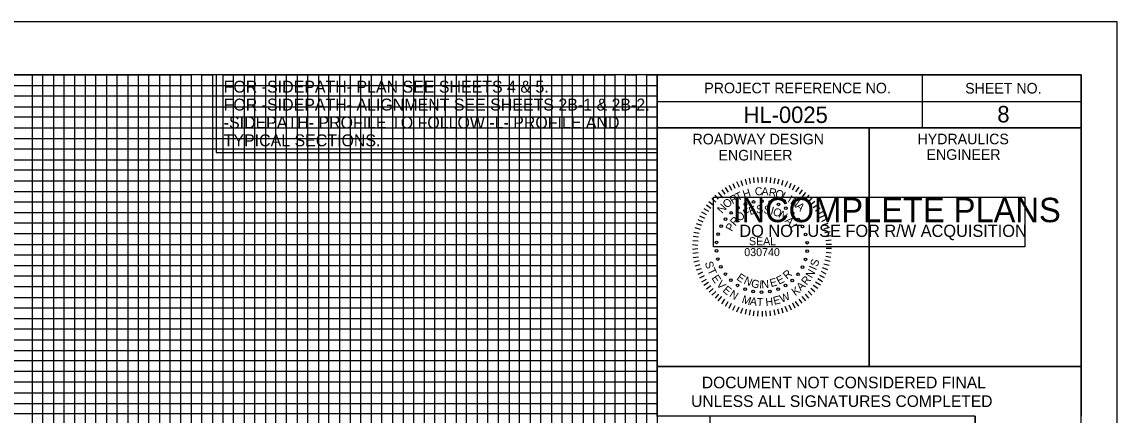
# Model space of a CAD drawing. Extents: x 1524869 to 1526553, y 501099 to 502199.
# Drawn here: x 1526036 to 1526553, y 502013 to 502199 of the extents above; entities that cross this region are included whole.
import ezdxf

# ---------------------------------------------------------------- set-up
doc = ezdxf.new("R2010")
doc.units = 0
for name, color, linetype in [('Old_Level_9', 7, 'Continuous'), ('Prop Grid Mask', 7, 'Continuous'), ('Prop Horizontal Alignment Curve and Spiral Data', 7, 'Continuous'), ('Sheet Data Field CELL', 7, 'Continuous'), ('Sheet Layout Profile Border Port 1', 7, 'Continuous'), ('Sheet Plot Border Outside CELL', 7, 'Continuous'), ('Sheet Profile CELL', 7, 'Continuous'), ('Sheet Profile Grid Major CELL', 7, 'Continuous'), ('Sheet Profile Grid Middle CELL', 7, 'Continuous'), ('Sheet Profile Grid Minor CELL', 7, 'Continuous'), ('Sheet Sticker Exception Certification CELL', 7, 'Continuous'), ('Sheet Sticker Incomplete CELL', 7, 'Continuous')]:
    doc.layers.add(name, color=color, linetype=linetype)

msp = doc.modelspace()

# ---------------------------------------------------------------- linework, layer by layer
at = {"layer": 'Old_Level_9'}
for p, q in [((1526369.96, 502121.58), (1526371.16, 502119.18)), ((1526371.76, 502122.38), (1526372.66, 502120.08)), ((1526373.46, 502123.18), (1526374.66, 502120.78)), ((1526375.56, 502123.78), (1526376.26, 502121.38)), ((1526377.46, 502124.38), (1526378.16, 502121.88)), ((1526379.36, 502124.78), (1526379.86, 502122.38)), ((1526381.46, 502125.08), (1526381.66, 502122.68)), ((1526383.36, 502125.18), (1526383.66, 502122.78)), ((1526385.46, 502125.38), (1526385.46, 502122.78)), ((1526387.56, 502125.38), (1526387.26, 502122.78)), ((1526389.46, 502125.08), (1526389.26, 502122.68)), ((1526391.56, 502124.78), (1526391.06, 502122.38)), ((1526393.46, 502124.38), (1526392.76, 502121.98)), ((1526395.36, 502123.78), (1526394.66, 502121.38)), ((1526397.46, 502123.18), (1526396.26, 502120.78)), ((1526399.16, 502122.38), (1526398.26, 502120.08)), ((1526400.96, 502121.58), (1526399.76, 502119.18)), ((1526363.26, 502116.78), (1526364.86, 502114.88)), ((1526364.86, 502118.08), (1526366.46, 502115.98)), ((1526366.46, 502119.28), (1526367.96, 502117.28)), ((1526368.06, 502120.38), (1526369.56, 502118.18)), ((1526402.86, 502120.58), (1526401.36, 502118.38)), ((1526404.46, 502119.28), (1526402.96, 502117.28)), ((1526406.06, 502118.08), (1526404.46, 502116.08)), ((1526407.66, 502116.78), (1526406.06, 502114.98)), ((1526409.06, 502115.48), (1526407.26, 502113.58)), ((1526358.06, 502110.58), (1526360.26, 502109.28)), ((1526359.36, 502112.28), (1526361.26, 502110.68)), ((1526360.46, 502113.88), (1526362.36, 502112.18)), ((1526361.86, 502115.28), (1526363.66, 502113.58)), ((1526410.46, 502113.88), (1526408.56, 502112.28)), ((1526411.76, 502112.28), (1526409.66, 502110.88)), ((1526412.86, 502110.68), (1526410.76, 502109.28)), ((1526355.16, 502105.28), (1526357.56, 502104.28)), ((1526355.96, 502107.08), (1526358.36, 502105.88)), ((1526356.96, 502108.98), (1526359.16, 502107.68)), ((1526413.96, 502108.98), (1526411.76, 502107.68)), ((1526414.96, 502107.18), (1526412.56, 502106.08)), ((1526415.76, 502105.48), (1526413.56, 502104.28)), ((1526353.76, 502101.48), (1526356.26, 502100.78)), ((1526354.36, 502103.38), (1526356.96, 502102.58)), ((1526416.56, 502103.38), (1526413.96, 502102.58)), ((1526417.16, 502101.48), (1526414.66, 502100.78)), ((1526352.76, 502095.38), (1526355.36, 502095.28)), ((1526352.96, 502097.48), (1526355.46, 502097.18)), ((1526353.26, 502099.38), (1526355.76, 502098.88)), ((1526417.66, 502099.58), (1526415.16, 502099.08)), ((1526417.96, 502097.68), (1526415.56, 502097.18)), ((1526418.16, 502095.58), (1526415.56, 502095.28)), ((1526352.66, 502093.48), (1526355.16, 502093.28)), ((1526352.66, 502091.38), (1526355.16, 502091.58)), ((1526352.76, 502089.38), (1526355.36, 502089.68)), ((1526418.26, 502093.48), (1526415.76, 502093.48)), ((1526418.26, 502091.58), (1526415.76, 502091.58)), ((1526418.16, 502089.48), (1526415.76, 502089.68)), ((1526352.96, 502087.38), (1526355.46, 502087.78)), ((1526353.26, 502085.38), (1526355.76, 502085.98)), ((1526417.66, 502085.48), (1526415.16, 502086.18)), ((1526417.96, 502087.38), (1526415.56, 502087.88)), ((1526353.86, 502083.48), (1526356.26, 502084.08)), ((1526354.56, 502081.58), (1526356.96, 502082.28)), ((1526355.36, 502079.58), (1526357.56, 502080.58)), ((1526415.76, 502079.58), (1526413.56, 502080.78)), ((1526416.56, 502081.58), (1526413.96, 502082.48)), ((1526417.16, 502083.58), (1526414.66, 502084.28)), ((1526356.16, 502077.88), (1526358.36, 502078.98)), ((1526357.06, 502075.98), (1526359.36, 502077.18)), ((1526358.06, 502074.38), (1526360.26, 502075.68)), ((1526359.36, 502072.58), (1526361.36, 502074.18)), ((1526411.76, 502072.78), (1526409.66, 502074.18)), ((1526413.06, 502074.38), (1526410.76, 502075.78)), ((1526413.96, 502075.98), (1526411.76, 502077.38)), ((1526414.96, 502077.88), (1526412.76, 502078.98)), ((1526360.56, 502070.98), (1526362.46, 502072.78)), ((1526361.86, 502069.58), (1526363.76, 502071.28)), ((1526363.46, 502068.18), (1526365.06, 502070.08)), ((1526364.86, 502066.88), (1526366.46, 502068.98)), ((1526406.16, 502066.88), (1526404.46, 502068.98)), ((1526407.66, 502068.28), (1526406.06, 502070.08)), ((1526409.06, 502069.58), (1526407.26, 502071.48)), ((1526410.46, 502071.18), (1526408.56, 502072.78)), ((1526366.46, 502065.58), (1526367.96, 502067.68)), ((1526368.26, 502064.48), (1526369.56, 502066.68)), ((1526369.96, 502063.48), (1526371.16, 502065.78)), ((1526371.76, 502062.58), (1526372.86, 502064.78)), ((1526373.66, 502061.78), (1526374.66, 502064.18)), ((1526397.46, 502061.78), (1526396.46, 502064.28)), ((1526399.36, 502062.58), (1526398.26, 502064.98)), ((1526401.06, 502063.48), (1526399.96, 502065.78)), ((1526402.86, 502064.48), (1526401.36, 502066.68)), ((1526404.46, 502065.78), (1526402.96, 502067.78)), ((1526375.56, 502061.08), (1526376.36, 502063.48)), ((1526377.66, 502060.68), (1526378.16, 502063.08)), ((1526379.56, 502060.18), (1526380.06, 502062.68)), ((1526381.46, 502059.88), (1526381.76, 502062.28)), ((1526383.56, 502059.68), (1526383.66, 502062.28)), ((1526385.66, 502059.58), (1526385.66, 502062.08)), ((1526387.56, 502059.68), (1526387.36, 502062.28)), ((1526389.56, 502059.88), (1526389.26, 502062.28)), ((1526391.66, 502060.18), (1526391.16, 502062.68)), ((1526393.56, 502060.68), (1526392.96, 502063.08)), ((1526395.46, 502061.08), (1526394.86, 502063.48))]:
    msp.add_line(p, q, dxfattribs=at)
for centre in [(1526374.13, 502110.79), (1526377.69, 502112.54), (1526381.51, 502113.61), (1526385.46, 502113.96), (1526389.41, 502113.58), (1526393.22, 502112.48), (1526396.76, 502110.7), (1526368.28, 502105.49), (1526370.96, 502108.41), (1526399.91, 502108.3), (1526402.57, 502105.36), (1526366.18, 502102.13), (1526404.65, 502101.98), (1526363.98, 502094.54), (1526364.73, 502098.44), (1526406.07, 502098.28), (1526406.78, 502094.38), (1526363.97, 502090.58), (1526406.76, 502090.41), (1526364.68, 502086.68), (1526406.02, 502086.51), (1526366.1, 502082.97), (1526368.18, 502079.59), (1526402.47, 502079.46), (1526404.57, 502082.82), (1526370.84, 502076.65), (1526373.99, 502074.25), (1526396.61, 502074.16), (1526399.79, 502076.54), (1526377.53, 502072.47), (1526381.34, 502071.37), (1526385.29, 502070.99), (1526389.24, 502071.34), (1526393.06, 502072.41)]:
    msp.add_circle(centre, 0.63, dxfattribs=at)
at = {"layer": 'Prop Grid Mask'}
msp.add_lwpolyline([(1526127.84, 502137.02), (1526336.03, 502137.02), (1526336.03, 502173.56), (1526127.84, 502173.56)], close=True, dxfattribs=at)
at = {"layer": 'Sheet Layout Profile Border Port 1'}
msp.add_lwpolyline([(1525086.08, 502173.56), (1525086.08, 501673.56), (1526486.08, 501673.56), (1526486.08, 502012.51), (1526336.03, 502012.51), (1526336.08, 502173.56)], close=True, dxfattribs=at)
at = {"layer": 'Sheet Plot Border Outside CELL'}
msp.add_lwpolyline([(1524869.08, 501098.56), (1526553.08, 501098.56), (1526553.08, 502198.56), (1524869.08, 502198.56)], close=True, dxfattribs=at)
at = {"layer": 'Sheet Profile CELL'}
for p, q in [((1526461.08, 502173.51), (1526461.08, 502148.51)), ((1526336.03, 502161.01), (1526536.08, 502161.01)), ((1526436.08, 502148.51), (1526436.08, 502036.06))]:
    msp.add_line(p, q, dxfattribs=at)
for points in [[(1526536.08, 502173.56), (1525036.08, 502173.56), (1525036.08, 501123.56), (1526536.08, 501123.56)], [(1526336.03, 502173.56), (1526536.08, 502173.56), (1526536.08, 502148.51), (1526336.03, 502148.51)], [(1526336.03, 502148.51), (1526436.08, 502148.51), (1526436.08, 502036.01), (1526336.03, 502036.01)], [(1526436.08, 502148.51), (1526536.08, 502148.51), (1526536.08, 502036.01), (1526436.08, 502036.01)]]:
    msp.add_lwpolyline(points, close=True, dxfattribs=at)
at = {"layer": 'Sheet Profile Grid Major CELL'}
for p, q in [((1526186.03, 502173.56), (1526236.03, 502173.56)), ((1526226.97, 502173.56), (1526276.97, 502173.56))]:
    msp.add_line(p, q, dxfattribs=at)
for points in [[(1526036.08, 502173.56), (1526086.08, 502173.56), (1526086.08, 501673.56), (1526136.08, 501673.56), (1526136.08, 502173.56), (1526186.08, 502173.56), (1526186.08, 501673.56), (1526236.08, 501673.56), (1526236.08, 502173.56), (1526286.08, 502173.56), (1526286.08, 501673.56), (1526336.08, 501673.56), (1526336.08, 502173.56), (1526362.38, 502173.56)], [(1525036.08, 502123.56), (1526336.08, 502123.56)], [(1526336.08, 502073.56), (1525036.08, 502073.56), (1525036.08, 502023.56), (1526336.08, 502023.56)], [(1526486.08, 502012.51), (1526486.08, 501673.56), (1526536.08, 501673.56), (1526536.08, 502023.56)]]:
    msp.add_lwpolyline(points, dxfattribs=at)
at = {"layer": 'Sheet Profile Grid Middle CELL'}
msp.add_line((1525036.08, 502148.56), (1526336.03, 502148.56), dxfattribs=at)
for points in [[(1526011.08, 501673.56), (1526061.08, 501673.56), (1526061.08, 502173.56), (1526111.08, 502173.56), (1526111.08, 501673.56), (1526161.08, 501673.56), (1526161.08, 502173.56), (1526211.08, 502173.56), (1526211.08, 501673.56), (1526261.08, 501673.56), (1526261.08, 502173.56), (1526311.08, 502173.56), (1526311.08, 501673.56), (1526361.08, 501673.56), (1526361.08, 502012.51)], [(1526336.08, 502098.56), (1525036.08, 502098.56), (1525036.08, 502048.56), (1526336.08, 502048.56)]]:
    msp.add_lwpolyline(points, dxfattribs=at)
at = {"layer": 'Sheet Profile Grid Minor CELL'}
for p, q in [((1525086.08, 502168.56), (1526336.08, 502168.56)), ((1526336.08, 502163.56), (1525086.08, 502163.21)), ((1525086.08, 502158.56), (1526336.08, 502158.56)), ((1526336.03, 502038.56), (1525086.08, 502038.56)), ((1526336.08, 502033.56), (1525086.08, 502033.56)), ((1526336.08, 502028.56), (1525086.08, 502028.56)), ((1525086.08, 502018.56), (1526336.08, 502018.56)), ((1526336.08, 502013.56), (1525086.08, 502013.56))]:
    msp.add_line(p, q, dxfattribs=at)
for points in [[(1526031.08, 502173.56), (1526041.08, 502173.56), (1526041.08, 501673.56)], [(1526046.08, 501673.56), (1526046.08, 502173.56), (1526051.08, 502173.56), (1526051.08, 501673.56)], [(1526056.08, 501673.56), (1526056.08, 502173.56), (1526066.08, 502173.56), (1526066.08, 501673.56)], [(1526071.08, 501673.56), (1526071.08, 502173.56), (1526076.08, 502173.56), (1526076.08, 501673.56)], [(1526081.08, 501673.56), (1526081.08, 502173.56), (1526091.08, 502173.56), (1526091.08, 501673.56)], [(1526096.08, 501673.56), (1526096.08, 502173.56), (1526101.08, 502173.56), (1526101.08, 501673.56)], [(1526106.08, 501673.56), (1526106.08, 502173.56), (1526116.08, 502173.56), (1526116.08, 501673.56)], [(1526121.08, 501673.56), (1526121.08, 502173.56), (1526126.08, 502173.56), (1526126.08, 501673.56)], [(1526131.08, 501673.56), (1526131.08, 502173.56), (1526141.08, 502173.56), (1526141.08, 501673.56)], [(1526146.08, 501673.56), (1526146.08, 502173.56), (1526151.08, 502173.56), (1526151.08, 501673.56)], [(1526156.08, 501673.56), (1526156.08, 502173.56), (1526166.08, 502173.56), (1526166.08, 501673.56)], [(1526171.08, 501673.56), (1526171.08, 502173.56), (1526176.08, 502173.56), (1526176.08, 501673.56)], [(1526181.08, 501673.56), (1526181.08, 502173.56), (1526191.08, 502173.56), (1526191.08, 501673.56)], [(1526196.08, 501673.56), (1526196.08, 502173.56), (1526201.08, 502173.56), (1526201.08, 501673.56)], [(1526206.08, 501673.56), (1526206.08, 502173.56), (1526216.08, 502173.56), (1526216.08, 501673.56)], [(1526221.08, 501673.56), (1526221.08, 502173.56), (1526226.08, 502173.56), (1526226.08, 501673.56)], [(1526231.08, 501673.56), (1526231.08, 502173.56), (1526241.08, 502173.56), (1526241.08, 501673.56)], [(1526246.08, 501673.56), (1526246.08, 502173.56), (1526251.08, 502173.56), (1526251.08, 501673.56)], [(1526256.08, 501673.56), (1526256.08, 502173.56), (1526266.08, 502173.56), (1526266.08, 501673.56)], [(1526271.08, 501673.56), (1526271.08, 502173.56), (1526276.08, 502173.56), (1526276.08, 501673.56)], [(1526281.08, 501673.56), (1526281.08, 502173.56), (1526291.08, 502173.56), (1526291.08, 501673.56)], [(1526296.08, 501673.56), (1526296.08, 502173.56), (1526301.08, 502173.56), (1526301.08, 501673.56)], [(1526306.08, 501673.56), (1526306.08, 502173.56), (1526316.08, 502173.56), (1526316.08, 501673.56)], [(1526321.08, 501673.56), (1526321.08, 502173.56), (1526326.08, 502173.56), (1526326.08, 501673.56)], [(1526331.08, 501673.56), (1526331.08, 502173.56), (1526341.08, 502173.56)], [(1526336.08, 502153.56), (1525086.08, 502153.56), (1525086.08, 502143.56), (1526336.08, 502143.56)], [(1526336.03, 502138.56), (1525086.08, 502138.56), (1525086.08, 502133.56), (1526336.08, 502133.56)], [(1526336.08, 502128.56), (1525086.08, 502128.56), (1525086.08, 502118.56), (1526336.08, 502118.56)], [(1526336.08, 502113.56), (1525086.08, 502113.56), (1525086.08, 502108.56), (1526336.08, 502108.56)], [(1526336.08, 502103.56), (1525086.08, 502103.56), (1525086.08, 502093.56), (1526336.08, 502093.56)], [(1526336.08, 502088.56), (1525086.08, 502088.56), (1525086.08, 502083.56), (1526336.08, 502083.56)], [(1526336.08, 502078.56), (1525086.08, 502078.56), (1525086.08, 502068.56), (1526336.08, 502068.56)], [(1526336.08, 502063.46), (1525086.18, 502063.46), (1525086.18, 502058.56), (1526336.08, 502058.56)], [(1526336.08, 502053.56), (1525086.08, 502053.56), (1525086.08, 502043.56), (1526336.08, 502043.56)]]:
    msp.add_lwpolyline(points, dxfattribs=at)
at = {"layer": 'Sheet Sticker Exception Certification CELL'}
for p, q in [((1526336.03, 502012.51), (1526336.03, 502036.01)), ((1526336.03, 502036.01), (1526536.07, 502036.01)), ((1526336.03, 502012.51), (1526336.03, 502036.01)), ((1526336.03, 502036.01), (1526536.07, 502036.01)), ((1526536.07, 502036), (1526536.07, 502012.5)), ((1526536.07, 502036), (1526536.07, 502012.5))]:
    msp.add_line(p, q, dxfattribs=at)
at = {"layer": 'Sheet Sticker Incomplete CELL'}
msp.add_lwpolyline([(1526362.6, 502092.36), (1526362.6, 502115.86), (1526509.6, 502115.86), (1526509.6, 502092.36)], close=True, dxfattribs=at)

# ---------------------------------------------------------------- texts
at = {"layer": 'Old_Level_9'}
for s, height, rotation, p in [('C', 3.78, 4.9399, (1526382.26, 502116.58)), ('R', 3.78, 32.1754, (1526371.56, 502112.48)), ('T', 3.78, 25.4358, (1526373.96, 502113.88)), ('H', 3.78, 17.7433, (1526377.06, 502115.28)), ('A', 3.78, 357.9749, (1526385.16, 502116.78)), ('R', 3.78, 350.0216, (1526388.46, 502116.58)), ('O', 3.78, 343.0868, (1526391.36, 502116.08)), ('L', 3.78, 335.7459, (1526394.36, 502115.18)), ('I', 3.78, 330.806, (1526397.26, 502113.78)), ('N', 3.78, 324.9038, (1526398.56, 502113.08)), ('N', 3.78, 48.0667, (1526366.66, 502107.88)), ('O', 3.78, 39.9442, (1526368.86, 502110.38)), ('F', 3.76, 26.4, (1526377.66, 502106.28)), ('E', 3.76, 16.5889, (1526379.86, 502107.38)), ('S', 3.76, 4.468, (1526382.86, 502108.18)), ('S', 3.76, 353.0415, (1526386.06, 502108.28)), ('I', 3.76, 345.4821, (1526389.26, 502107.88)), ('O', 3.76, 337.8749, (1526390.26, 502107.68)), ('A', 3.78, 317.0051, (1526401.06, 502111.18)), ('R', 3.76, 49.7478, (1526372.86, 502101.98)), ('O', 3.76, 38.2518, (1526374.76, 502104.18)), ('N', 3.76, 327.393, (1526392.96, 502106.58)), ('A', 3.76, 313.9438, (1526395.96, 502104.48)), ('P', 3.76, 60.1236, (1526371.26, 502099.38)), ('L', 3.76, 301.5323, (1526398.36, 502101.78)), ('S', 3.78, 288.212, (1526358.41, 502084.9)), ('S', 3.78, 72.2579, (1526411.64, 502082.79)), ('T', 3.78, 295.6244, (1526359.6, 502081.38)), ('E', 3.78, 303.8225, (1526361.47, 502077.7)), ('E', 3.76, 324.8692, (1526373.16, 502077.18)), ('R', 3.76, 40.3493, (1526397.26, 502076.88)), ('N', 3.78, 59.3726, (1526409.01, 502077.3)), ('I', 3.78, 66.0464, (1526410.94, 502081.1)), ('V', 3.78, 311.9298, (1526363.73, 502074.52)), ('E', 3.78, 320.2312, (1526366.62, 502071.55)), ('N', 3.76, 336.0584, (1526376.56, 502075.18)), ('G', 3.76, 347.4812, (1526380.06, 502073.58)), ('I', 3.76, 355.6246, (1526384.06, 502072.88)), ('N', 3.76, 3.1278, (1526385.26, 502072.88)), ('E', 3.76, 15.8057, (1526389.76, 502073.38)), ('E', 3.76, 27.1568, (1526393.46, 502074.48)), ('A', 3.78, 43.5217, (1526403.79, 502071.39)), ('R', 3.78, 51.1503, (1526406.55, 502074.06)), ('N', 3.78, 328.329, (1526369.75, 502069.12)), ('M', 3.78, 342.337, (1526375.66, 502066.12)), ('E', 3.78, 14.1648, (1526391.25, 502065)), ('W', 3.78, 22.0058, (1526394.71, 502065.96)), ('K', 3.78, 36.141, (1526401.16, 502069.12)), ('A', 3.78, 350.1822, (1526379.55, 502065.09)), ('T', 3.78, 357.3866, (1526382.96, 502064.53)), ('H', 3.78, 6.0112, (1526387.31, 502064.42))]:
    msp.add_text(s, height=height, rotation=rotation, dxfattribs=at).set_placement(p)
for s, p in [('SEAL', (1526379.32, 502093.21)), ('030740', (1526377.12, 502088.05))]:
    msp.add_text(s, height=3.759, dxfattribs=at).set_placement(p)
at = {"layer": 'Prop Horizontal Alignment Curve and Spiral Data'}
for s, p in [('FOR -SIDEPATH- PLAN SEE SHEETS 4 & 5.', (1526131.4, 502165.18)), ('FOR -SIDEPATH- ALIGNMENT SEE SHEETS 2B-1 & 2B-2.', (1526131.4, 502156.74)), ('-SIDEPATH- PROFILE TO FOLLOW -L- PROFILE AND', (1526131.4, 502148.3)), ('TYPICAL SECTIONS.', (1526131.4, 502139.87))]:
    msp.add_text(s, height=5.625, rotation=360, dxfattribs=at).set_placement(p)
at = {"layer": 'Sheet Data Field CELL'}
for s, p in [('HL-0025', (1526376.78, 502150.87)), ('8', (1526496.55, 502151.17))]:
    msp.add_text(s, height=7.75, dxfattribs=at).set_placement(p)
at = {"layer": 'Sheet Profile CELL'}
for s, height, p in [('PROJECT REFERENCE NO.', 5.0001, (1526358.24, 502164.87)), ('SHEET NO.', 5, (1526481.39, 502164.77)), ('ROADWAY DESIGN', 5.0001, (1526352.69, 502140.77)), ('HYDRAULICS', 5, (1526458.89, 502140.82)), ('ENGINEER', 5, (1526364.94, 502133.17)), ('ENGINEER', 5, (1526463.14, 502133.47))]:
    msp.add_text(s, height=height, dxfattribs=at).set_placement(p)
at = {"layer": 'Sheet Sticker Exception Certification CELL'}
for s, p in [('DOCUMENT NOT CONSIDERED FINAL', (1526357.1, 502025.67)), ('DOCUMENT NOT CONSIDERED FINAL', (1526357.1, 502025.67)), ('UNLESS ALL SIGNATURES COMPLETED', (1526352.03, 502016.87)), ('UNLESS ALL SIGNATURES COMPLETED', (1526352.03, 502016.87))]:
    msp.add_text(s, height=5.5, dxfattribs=at).set_placement(p)
at = {"layer": 'Sheet Sticker Incomplete CELL'}
for s, height, p in [('INCOMPLETE PLANS', 11.52, (1526371.55, 502104.06)), ('DO NOT USE FOR R/W ACQUISITION', 5.76, (1526374.8, 502097.11))]:
    msp.add_text(s, height=height, dxfattribs=at).set_placement(p)

doc.saveas('drawing.dxf')
